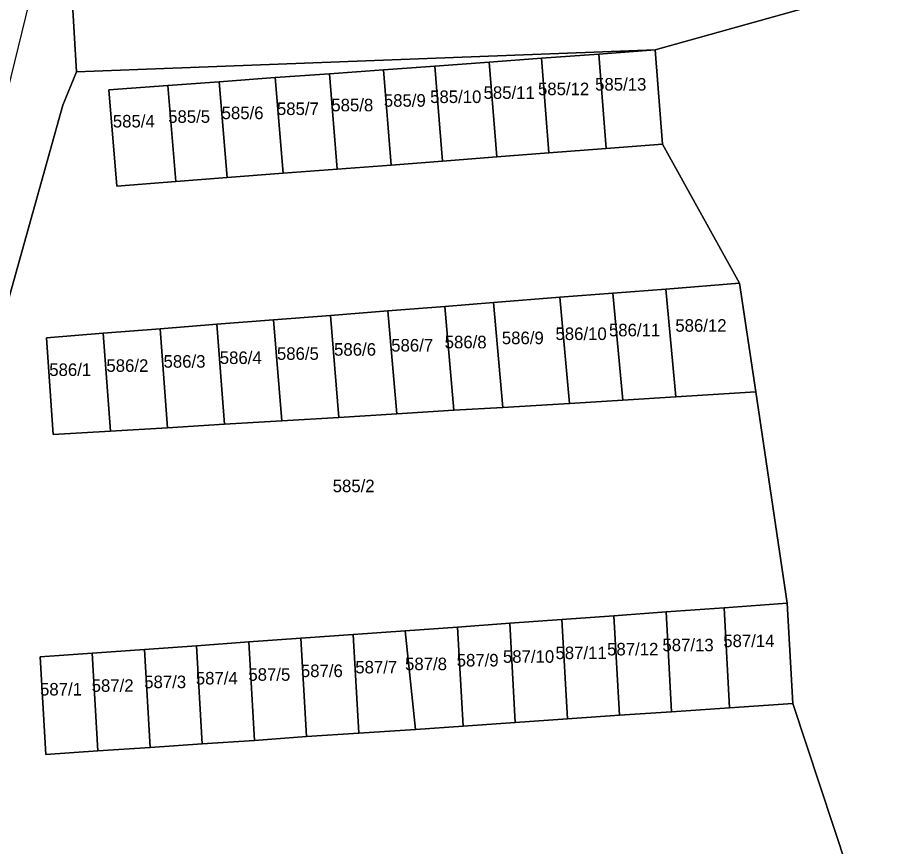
# Model space of a CAD drawing. Extents: x -873642 to -872917, y -1012962 to -1012567.
# Drawn here: x -873069.4 to -873009.9, y -1012699.6 to -1012643.4 of the extents above; entities that cross this region are included whole.
import ezdxf

# ---------------------------------------------------------------- set-up
doc = ezdxf.new("R2010")
doc.units = 0
for name, color, linetype in [('cisla_parcelni_kn', 7, 'Continuous'), ('osy_ulic', 7, 'Continuous'), ('parcely_kn', 7, 'Continuous'), ('stavebni_objekty_ostatni', 7, 'Continuous')]:
    doc.layers.add(name, color=color, linetype=linetype)

msp = doc.modelspace()

# ---------------------------------------------------------------- linework, layer by layer
at = {"layer": 'osy_ulic'}
msp.add_lwpolyline([(-873411.85, -1012822.53), (-873317.85, -1012788.44), (-873277.23, -1012773.91), (-873252.76, -1012767.01), (-873201.18, -1012755.57), (-873115.6, -1012739.3), (-873104.65, -1012731.3), (-873088.93, -1012706.26), (-873080.41, -1012681.66), (-873071.61, -1012653.78), (-873070.57, -1012650.45), (-873066.08, -1012632.13), (-873063.74, -1012625.63), (-873059.56, -1012597.3)], dxfattribs=at)
at = {"layer": 'parcely_kn'}
for points in [[(-873047.57, -1012601.38), (-872987.5, -1012597.44), (-872963.92, -1012595.9), (-872964.43, -1012596.64), (-872989.57, -1012634.71), (-872990.98, -1012635.74), (-873026.14, -1012645.58), (-873065.38, -1012647.07), (-873065.7, -1012641.7), (-873062.75, -1012637.7), (-873058.34, -1012622.19), (-873059.76, -1012619.22), (-873054.28, -1012608.24), (-873052.37, -1012604.41), (-873050.31, -1012602.24)], [(-873047.57, -1012601.38), (-872987.5, -1012597.44), (-872963.92, -1012595.9), (-872964.43, -1012596.64), (-872989.57, -1012634.71), (-872990.98, -1012635.74), (-873026.14, -1012645.58), (-873065.38, -1012647.07), (-873065.7, -1012641.7), (-873062.75, -1012637.7), (-873058.34, -1012622.19), (-873059.76, -1012619.22), (-873054.28, -1012608.24), (-873052.37, -1012604.41), (-873050.31, -1012602.24)], [(-873026.14, -1012645.58), (-873025.64, -1012651.97), (-873029.46, -1012652.26), (-873029.97, -1012645.86)], [(-873026.14, -1012645.58), (-873025.64, -1012651.97), (-873029.46, -1012652.26), (-873029.97, -1012645.86)], [(-873033.86, -1012646.14), (-873033.35, -1012652.56), (-873036.88, -1012652.83), (-873037.4, -1012646.4)], [(-873033.86, -1012646.14), (-873033.35, -1012652.56), (-873036.88, -1012652.83), (-873037.4, -1012646.4)], [(-873029.97, -1012645.86), (-873029.46, -1012652.26), (-873033.35, -1012652.56), (-873033.86, -1012646.14)], [(-873029.97, -1012645.86), (-873029.46, -1012652.26), (-873033.35, -1012652.56), (-873033.86, -1012646.14)], [(-873041.08, -1012646.67), (-873040.56, -1012653.11), (-873044.05, -1012653.38), (-873044.57, -1012646.92)], [(-873041.08, -1012646.67), (-873040.56, -1012653.11), (-873044.05, -1012653.38), (-873044.57, -1012646.92)], [(-873037.4, -1012646.4), (-873036.88, -1012652.83), (-873040.56, -1012653.11), (-873041.08, -1012646.67)], [(-873037.4, -1012646.4), (-873036.88, -1012652.83), (-873040.56, -1012653.11), (-873041.08, -1012646.67)], [(-873051.91, -1012647.45), (-873051.38, -1012653.94), (-873055.17, -1012654.23), (-873055.72, -1012647.73)], [(-873051.91, -1012647.45), (-873051.38, -1012653.94), (-873055.17, -1012654.23), (-873055.72, -1012647.73)], [(-873048.23, -1012647.19), (-873047.7, -1012653.66), (-873051.38, -1012653.94), (-873051.91, -1012647.45)], [(-873048.23, -1012647.19), (-873047.7, -1012653.66), (-873051.38, -1012653.94), (-873051.91, -1012647.45)], [(-873044.57, -1012646.92), (-873044.05, -1012653.38), (-873047.7, -1012653.66), (-873048.23, -1012647.19)], [(-873044.57, -1012646.92), (-873044.05, -1012653.38), (-873047.7, -1012653.66), (-873048.23, -1012647.19)], [(-873059.19, -1012647.98), (-873058.65, -1012654.49), (-873062.64, -1012654.8), (-873063.19, -1012648.27)], [(-873059.19, -1012647.98), (-873058.65, -1012654.49), (-873062.64, -1012654.8), (-873063.19, -1012648.27)], [(-873055.72, -1012647.73), (-873055.17, -1012654.23), (-873058.65, -1012654.49), (-873059.19, -1012647.98)], [(-873055.72, -1012647.73), (-873055.17, -1012654.23), (-873058.65, -1012654.49), (-873059.19, -1012647.98)], [(-873020.42, -1012661.39), (-873019.32, -1012668.75), (-873024.74, -1012669.09), (-873025.43, -1012661.78)], [(-873020.42, -1012661.39), (-873019.32, -1012668.75), (-873024.74, -1012669.09), (-873025.43, -1012661.78)], [(-873029.02, -1012662.06), (-873028.33, -1012669.31), (-873031.96, -1012669.53), (-873032.62, -1012662.34)], [(-873029.02, -1012662.06), (-873028.33, -1012669.31), (-873031.96, -1012669.53), (-873032.62, -1012662.34)], [(-873029.02, -1012662.06), (-873025.43, -1012661.78), (-873024.74, -1012669.09), (-873028.33, -1012669.31)], [(-873029.02, -1012662.06), (-873025.43, -1012661.78), (-873024.74, -1012669.09), (-873028.33, -1012669.31)], [(-873037.12, -1012662.7), (-873036.48, -1012669.8), (-873039.8, -1012670), (-873040.42, -1012662.96)], [(-873037.12, -1012662.7), (-873036.48, -1012669.8), (-873039.8, -1012670), (-873040.42, -1012662.96)], [(-873032.62, -1012662.34), (-873031.96, -1012669.53), (-873036.48, -1012669.8), (-873037.12, -1012662.7)], [(-873032.62, -1012662.34), (-873031.96, -1012669.53), (-873036.48, -1012669.8), (-873037.12, -1012662.7)], [(-873044.27, -1012663.26), (-873043.67, -1012670.24), (-873047.6, -1012670.48), (-873048.17, -1012663.57)], [(-873044.27, -1012663.26), (-873043.67, -1012670.24), (-873047.6, -1012670.48), (-873048.17, -1012663.57)], [(-873040.42, -1012662.96), (-873039.8, -1012670), (-873043.67, -1012670.24), (-873044.27, -1012663.26)], [(-873040.42, -1012662.96), (-873039.8, -1012670), (-873043.67, -1012670.24), (-873044.27, -1012663.26)], [(-873052.02, -1012663.87), (-873051.47, -1012670.71), (-873055.34, -1012670.95), (-873055.87, -1012664.17)], [(-873052.02, -1012663.87), (-873051.47, -1012670.71), (-873055.34, -1012670.95), (-873055.87, -1012664.17)], [(-873048.17, -1012663.57), (-873047.6, -1012670.48), (-873051.47, -1012670.71), (-873052.02, -1012663.87)], [(-873048.17, -1012663.57), (-873047.6, -1012670.48), (-873051.47, -1012670.71), (-873052.02, -1012663.87)], [(-873059.72, -1012664.47), (-873059.22, -1012671.18), (-873063.09, -1012671.42), (-873063.57, -1012664.78)], [(-873059.72, -1012664.47), (-873059.22, -1012671.18), (-873063.09, -1012671.42), (-873063.57, -1012664.78)], [(-873055.87, -1012664.17), (-873055.34, -1012670.95), (-873059.22, -1012671.18), (-873059.72, -1012664.47)], [(-873055.87, -1012664.17), (-873055.34, -1012670.95), (-873059.22, -1012671.18), (-873059.72, -1012664.47)], [(-873063.57, -1012664.78), (-873063.09, -1012671.42), (-873066.96, -1012671.65), (-873067.42, -1012665.08)], [(-873063.57, -1012664.78), (-873063.09, -1012671.42), (-873066.96, -1012671.65), (-873067.42, -1012665.08)], [(-873017.19, -1012683.08), (-873016.82, -1012689.87), (-873021.11, -1012690.16), (-873021.48, -1012683.39)], [(-873017.19, -1012683.08), (-873016.82, -1012689.87), (-873021.11, -1012690.16), (-873021.48, -1012683.39)], [(-873025.4, -1012683.67), (-873025.03, -1012690.43), (-873028.57, -1012690.67), (-873028.94, -1012683.92)], [(-873025.4, -1012683.67), (-873025.03, -1012690.43), (-873028.57, -1012690.67), (-873028.94, -1012683.92)], [(-873021.48, -1012683.39), (-873021.11, -1012690.16), (-873025.03, -1012690.43), (-873025.4, -1012683.67)], [(-873021.48, -1012683.39), (-873021.11, -1012690.16), (-873025.03, -1012690.43), (-873025.4, -1012683.67)], [(-873032.48, -1012684.18), (-873032.1, -1012690.91), (-873035.64, -1012691.16), (-873036.01, -1012684.43)], [(-873032.48, -1012684.18), (-873032.1, -1012690.91), (-873035.64, -1012691.16), (-873036.01, -1012684.43)], [(-873028.94, -1012683.92), (-873028.57, -1012690.67), (-873032.1, -1012690.91), (-873032.48, -1012684.18)], [(-873028.94, -1012683.92), (-873028.57, -1012690.67), (-873032.1, -1012690.91), (-873032.48, -1012684.18)], [(-873039.55, -1012684.69), (-873039.17, -1012691.4), (-873042.41, -1012691.64), (-873043.09, -1012684.94)], [(-873039.55, -1012684.69), (-873039.17, -1012691.4), (-873042.41, -1012691.64), (-873043.09, -1012684.94)], [(-873036.01, -1012684.43), (-873035.64, -1012691.16), (-873039.17, -1012691.4), (-873039.55, -1012684.69)], [(-873036.01, -1012684.43), (-873035.64, -1012691.16), (-873039.17, -1012691.4), (-873039.55, -1012684.69)], [(-873050.17, -1012685.45), (-873049.78, -1012692.12), (-873053.32, -1012692.37), (-873053.71, -1012685.7)], [(-873050.17, -1012685.45), (-873049.78, -1012692.12), (-873053.32, -1012692.37), (-873053.71, -1012685.7)], [(-873046.63, -1012685.19), (-873046.25, -1012691.88), (-873049.78, -1012692.12), (-873050.17, -1012685.45)], [(-873046.63, -1012685.19), (-873046.25, -1012691.88), (-873049.78, -1012692.12), (-873050.17, -1012685.45)], [(-873043.09, -1012684.94), (-873042.41, -1012691.64), (-873046.25, -1012691.88), (-873046.63, -1012685.19)], [(-873043.09, -1012684.94), (-873042.41, -1012691.64), (-873046.25, -1012691.88), (-873046.63, -1012685.19)], [(-873057.25, -1012685.96), (-873056.86, -1012692.61), (-873060.39, -1012692.85), (-873060.78, -1012686.21)], [(-873057.25, -1012685.96), (-873056.86, -1012692.61), (-873060.39, -1012692.85), (-873060.78, -1012686.21)], [(-873053.71, -1012685.7), (-873053.32, -1012692.37), (-873056.86, -1012692.61), (-873057.25, -1012685.96)], [(-873053.71, -1012685.7), (-873053.32, -1012692.37), (-873056.86, -1012692.61), (-873057.25, -1012685.96)], [(-873064.32, -1012686.47), (-873063.93, -1012693.09), (-873067.47, -1012693.33), (-873067.86, -1012686.72)], [(-873064.32, -1012686.47), (-873063.93, -1012693.09), (-873067.47, -1012693.33), (-873067.86, -1012686.72)], [(-873060.78, -1012686.21), (-873060.39, -1012692.85), (-873063.93, -1012693.09), (-873064.32, -1012686.47)], [(-873060.78, -1012686.21), (-873060.39, -1012692.85), (-873063.93, -1012693.09), (-873064.32, -1012686.47)]]:
    msp.add_lwpolyline(points, close=True, dxfattribs=at)
for points in [[(-873079.43, -1012607.12), (-873054.9, -1012604.66), (-873052.37, -1012604.41), (-873054.28, -1012608.24), (-873059.76, -1012619.22), (-873058.34, -1012622.19), (-873062.75, -1012637.7), (-873065.7, -1012641.7), (-873065.38, -1012647.07), (-873066.31, -1012649.31), (-873079.09, -1012694.9), (-873083.74, -1012706.73), (-873087.64, -1012713.81), (-873091.65, -1012719.56), (-873097.47, -1012726.79), (-873099.7, -1012729.49), (-873101.03, -1012731.11), (-873105.65, -1012736.17), (-873110.07, -1012739.5), (-873114.5, -1012741.96), (-873122.26, -1012744.11), (-873135.01, -1012746.72), (-873148.18, -1012749.22), (-873185.58, -1012756.25)], [(-873079.43, -1012607.12), (-873054.9, -1012604.66), (-873052.37, -1012604.41), (-873054.28, -1012608.24), (-873059.76, -1012619.22), (-873058.34, -1012622.19), (-873062.75, -1012637.7), (-873065.7, -1012641.7), (-873065.38, -1012647.07), (-873066.31, -1012649.31), (-873079.09, -1012694.9), (-873083.74, -1012706.73), (-873087.64, -1012713.81), (-873091.65, -1012719.56), (-873097.47, -1012726.79), (-873099.7, -1012729.49), (-873101.03, -1012731.11), (-873105.65, -1012736.17), (-873110.07, -1012739.5), (-873114.5, -1012741.96), (-873122.26, -1012744.11), (-873135.01, -1012746.72), (-873148.18, -1012749.22), (-873185.58, -1012756.25)], [(-873074.59, -1012740.17), (-873069.33, -1012739.79), (-873065.48, -1012733.61), (-873030.18, -1012730.01), (-873032.33, -1012708.94), (-873028.33, -1012708.58), (-873024.28, -1012708.22), (-873020.29, -1012707.86), (-873016.29, -1012707.5), (-873012.61, -1012707.16), (-873013.12, -1012701), (-873016.82, -1012689.87), (-873017.19, -1012683.08), (-873019.32, -1012668.75), (-873020.42, -1012661.39), (-873025.64, -1012651.97), (-873026.14, -1012645.58), (-872990.98, -1012635.74)], [(-873074.59, -1012740.17), (-873069.33, -1012739.79), (-873065.48, -1012733.61), (-873030.18, -1012730.01), (-873032.33, -1012708.94), (-873028.33, -1012708.58), (-873024.28, -1012708.22), (-873020.29, -1012707.86), (-873016.29, -1012707.5), (-873012.61, -1012707.16), (-873013.12, -1012701), (-873016.82, -1012689.87), (-873017.19, -1012683.08), (-873019.32, -1012668.75), (-873020.42, -1012661.39), (-873025.64, -1012651.97), (-873026.14, -1012645.58), (-872990.98, -1012635.74)], [(-873079.09, -1012694.9), (-873066.31, -1012649.31), (-873065.38, -1012647.07), (-873026.14, -1012645.58), (-873029.97, -1012645.86), (-873033.86, -1012646.14), (-873037.4, -1012646.4), (-873041.08, -1012646.67), (-873044.57, -1012646.92), (-873048.23, -1012647.19), (-873051.91, -1012647.45), (-873055.72, -1012647.73), (-873059.19, -1012647.98), (-873063.19, -1012648.27), (-873062.64, -1012654.8), (-873058.65, -1012654.49), (-873055.17, -1012654.23), (-873051.38, -1012653.94), (-873047.7, -1012653.66), (-873044.05, -1012653.38), (-873040.56, -1012653.11), (-873036.88, -1012652.83), (-873033.35, -1012652.56), (-873029.46, -1012652.26), (-873025.64, -1012651.97), (-873020.42, -1012661.39), (-873025.43, -1012661.78), (-873029.02, -1012662.06), (-873032.62, -1012662.34), (-873037.12, -1012662.7), (-873040.42, -1012662.96), (-873044.27, -1012663.26), (-873048.17, -1012663.57), (-873052.02, -1012663.87), (-873055.87, -1012664.17), (-873059.72, -1012664.47), (-873063.57, -1012664.78), (-873067.42, -1012665.08), (-873066.96, -1012671.65), (-873063.09, -1012671.42), (-873059.22, -1012671.18), (-873055.34, -1012670.95), (-873051.47, -1012670.71), (-873047.6, -1012670.48), (-873043.67, -1012670.24), (-873039.8, -1012670), (-873036.48, -1012669.8), (-873031.96, -1012669.53), (-873028.33, -1012669.31), (-873024.74, -1012669.09), (-873019.32, -1012668.75), (-873017.19, -1012683.08), (-873021.48, -1012683.39), (-873025.4, -1012683.67), (-873028.94, -1012683.92), (-873032.48, -1012684.18), (-873036.01, -1012684.43), (-873039.55, -1012684.69), (-873043.09, -1012684.94), (-873046.63, -1012685.19), (-873050.17, -1012685.45), (-873053.71, -1012685.7), (-873057.25, -1012685.96), (-873060.78, -1012686.21), (-873064.32, -1012686.47), (-873067.86, -1012686.72), (-873067.47, -1012693.33), (-873063.93, -1012693.09), (-873060.39, -1012692.85), (-873056.86, -1012692.61), (-873053.32, -1012692.37), (-873049.78, -1012692.12), (-873046.25, -1012691.88), (-873042.41, -1012691.64), (-873039.17, -1012691.4), (-873035.64, -1012691.16), (-873032.1, -1012690.91), (-873028.57, -1012690.67), (-873025.03, -1012690.43), (-873021.11, -1012690.16), (-873016.82, -1012689.87), (-873013.12, -1012701)], [(-873079.09, -1012694.9), (-873066.31, -1012649.31), (-873065.38, -1012647.07), (-873026.14, -1012645.58), (-873029.97, -1012645.86), (-873033.86, -1012646.14), (-873037.4, -1012646.4), (-873041.08, -1012646.67), (-873044.57, -1012646.92), (-873048.23, -1012647.19), (-873051.91, -1012647.45), (-873055.72, -1012647.73), (-873059.19, -1012647.98), (-873063.19, -1012648.27), (-873062.64, -1012654.8), (-873058.65, -1012654.49), (-873055.17, -1012654.23), (-873051.38, -1012653.94), (-873047.7, -1012653.66), (-873044.05, -1012653.38), (-873040.56, -1012653.11), (-873036.88, -1012652.83), (-873033.35, -1012652.56), (-873029.46, -1012652.26), (-873025.64, -1012651.97), (-873020.42, -1012661.39), (-873025.43, -1012661.78), (-873029.02, -1012662.06), (-873032.62, -1012662.34), (-873037.12, -1012662.7), (-873040.42, -1012662.96), (-873044.27, -1012663.26), (-873048.17, -1012663.57), (-873052.02, -1012663.87), (-873055.87, -1012664.17), (-873059.72, -1012664.47), (-873063.57, -1012664.78), (-873067.42, -1012665.08), (-873066.96, -1012671.65), (-873063.09, -1012671.42), (-873059.22, -1012671.18), (-873055.34, -1012670.95), (-873051.47, -1012670.71), (-873047.6, -1012670.48), (-873043.67, -1012670.24), (-873039.8, -1012670), (-873036.48, -1012669.8), (-873031.96, -1012669.53), (-873028.33, -1012669.31), (-873024.74, -1012669.09), (-873019.32, -1012668.75), (-873017.19, -1012683.08), (-873021.48, -1012683.39), (-873025.4, -1012683.67), (-873028.94, -1012683.92), (-873032.48, -1012684.18), (-873036.01, -1012684.43), (-873039.55, -1012684.69), (-873043.09, -1012684.94), (-873046.63, -1012685.19), (-873050.17, -1012685.45), (-873053.71, -1012685.7), (-873057.25, -1012685.96), (-873060.78, -1012686.21), (-873064.32, -1012686.47), (-873067.86, -1012686.72), (-873067.47, -1012693.33), (-873063.93, -1012693.09), (-873060.39, -1012692.85), (-873056.86, -1012692.61), (-873053.32, -1012692.37), (-873049.78, -1012692.12), (-873046.25, -1012691.88), (-873042.41, -1012691.64), (-873039.17, -1012691.4), (-873035.64, -1012691.16), (-873032.1, -1012690.91), (-873028.57, -1012690.67), (-873025.03, -1012690.43), (-873021.11, -1012690.16), (-873016.82, -1012689.87), (-873013.12, -1012701)]]:
    msp.add_lwpolyline(points, dxfattribs=at)
at = {"layer": 'stavebni_objekty_ostatni'}
for points in [[(-873029.46, -1012652.26), (-873029.97, -1012645.86), (-873026.14, -1012645.58), (-873025.64, -1012651.97)], [(-873036.88, -1012652.83), (-873037.4, -1012646.4), (-873033.86, -1012646.14), (-873033.35, -1012652.56)], [(-873033.35, -1012652.56), (-873033.86, -1012646.14), (-873029.97, -1012645.86), (-873029.46, -1012652.26)], [(-873044.05, -1012653.38), (-873044.57, -1012646.92), (-873041.08, -1012646.67), (-873040.56, -1012653.11)], [(-873040.56, -1012653.11), (-873041.08, -1012646.67), (-873037.4, -1012646.4), (-873036.88, -1012652.83)], [(-873051.91, -1012647.45), (-873051.38, -1012653.94), (-873055.17, -1012654.23), (-873055.72, -1012647.73)], [(-873051.38, -1012653.94), (-873051.91, -1012647.45), (-873048.23, -1012647.19), (-873047.7, -1012653.66)], [(-873047.7, -1012653.66), (-873048.23, -1012647.19), (-873044.57, -1012646.92), (-873044.05, -1012653.38)], [(-873059.19, -1012647.98), (-873058.65, -1012654.49), (-873062.64, -1012654.8), (-873063.19, -1012648.27)], [(-873055.72, -1012647.73), (-873055.17, -1012654.23), (-873058.65, -1012654.49), (-873059.19, -1012647.98)], [(-873020.42, -1012661.39), (-873019.32, -1012668.75), (-873024.74, -1012669.09), (-873025.43, -1012661.78)], [(-873031.96, -1012669.53), (-873032.62, -1012662.34), (-873029.02, -1012662.06), (-873028.33, -1012669.31)], [(-873029.02, -1012662.06), (-873025.43, -1012661.78), (-873024.74, -1012669.09), (-873028.33, -1012669.31)], [(-873037.12, -1012662.7), (-873036.48, -1012669.8), (-873039.8, -1012670), (-873040.42, -1012662.96)], [(-873032.62, -1012662.34), (-873031.96, -1012669.53), (-873036.48, -1012669.8), (-873037.12, -1012662.7)], [(-873043.67, -1012670.24), (-873047.6, -1012670.48), (-873048.17, -1012663.57), (-873044.27, -1012663.26)], [(-873040.42, -1012662.96), (-873039.8, -1012670), (-873043.67, -1012670.24), (-873044.27, -1012663.26)], [(-873051.47, -1012670.71), (-873055.34, -1012670.95), (-873055.87, -1012664.17), (-873052.02, -1012663.87)], [(-873048.17, -1012663.57), (-873047.6, -1012670.48), (-873051.47, -1012670.71), (-873052.02, -1012663.87)], [(-873059.72, -1012664.47), (-873059.22, -1012671.18), (-873063.09, -1012671.42), (-873063.57, -1012664.78)], [(-873055.34, -1012670.95), (-873059.22, -1012671.18), (-873059.72, -1012664.47), (-873055.87, -1012664.17)], [(-873063.09, -1012671.42), (-873066.96, -1012671.65), (-873067.42, -1012665.08), (-873063.57, -1012664.78)], [(-873016.82, -1012689.87), (-873021.11, -1012690.16), (-873021.48, -1012683.39), (-873017.19, -1012683.08)], [(-873025.03, -1012690.43), (-873028.57, -1012690.67), (-873028.94, -1012683.92), (-873025.4, -1012683.67)], [(-873021.48, -1012683.39), (-873021.11, -1012690.16), (-873025.03, -1012690.43), (-873025.4, -1012683.67)], [(-873032.1, -1012690.91), (-873035.64, -1012691.16), (-873036.01, -1012684.43), (-873032.48, -1012684.18)], [(-873028.94, -1012683.92), (-873028.57, -1012690.67), (-873032.1, -1012690.91), (-873032.48, -1012684.18)], [(-873039.55, -1012684.69), (-873039.17, -1012691.4), (-873042.41, -1012691.64), (-873043.09, -1012684.94)], [(-873036.01, -1012684.43), (-873035.64, -1012691.16), (-873039.17, -1012691.4), (-873039.55, -1012684.69)], [(-873053.32, -1012692.37), (-873053.71, -1012685.7), (-873050.17, -1012685.45), (-873049.78, -1012692.12)], [(-873050.17, -1012685.45), (-873046.63, -1012685.19), (-873046.25, -1012691.88), (-873049.78, -1012692.12)], [(-873043.09, -1012684.94), (-873042.41, -1012691.64), (-873046.25, -1012691.88), (-873046.63, -1012685.19)], [(-873060.39, -1012692.85), (-873060.78, -1012686.21), (-873057.25, -1012685.96), (-873056.86, -1012692.61)], [(-873057.25, -1012685.96), (-873053.71, -1012685.7), (-873053.32, -1012692.37), (-873056.86, -1012692.61)], [(-873064.32, -1012686.47), (-873063.93, -1012693.09), (-873067.47, -1012693.33), (-873067.86, -1012686.72)], [(-873064.32, -1012686.47), (-873060.78, -1012686.21), (-873060.39, -1012692.85), (-873063.93, -1012693.09)]]:
    msp.add_lwpolyline(points, close=True, dxfattribs=at)

# ---------------------------------------------------------------- texts
at = {"layer": 'cisla_parcelni_kn'}
for s, p in [('585/13', (-873030.221, -1012648.331)), ('585/13', (-873030.221, -1012648.331)), ('585/11', (-873037.783, -1012648.894)), ('585/11', (-873037.783, -1012648.894)), ('585/12', (-873034.096, -1012648.644)), ('585/12', (-873034.096, -1012648.644)), ('585/9', (-873044.546, -1012649.425)), ('585/9', (-873044.546, -1012649.425)), ('585/10', (-873041.408, -1012649.175)), ('585/10', (-873041.408, -1012649.175)), ('585/7', (-873051.796, -1012649.988)), ('585/7', (-873051.796, -1012649.988)), ('585/8', (-873048.108, -1012649.738)), ('585/8', (-873048.108, -1012649.738)), ('585/5', (-873059.171, -1012650.519)), ('585/5', (-873059.171, -1012650.519)), ('585/6', (-873055.546, -1012650.269)), ('585/6', (-873055.546, -1012650.269)), ('585/4', (-873062.921, -1012650.831)), ('585/4', (-873062.921, -1012650.831)), ('586/11', (-873029.283, -1012664.988)), ('586/11', (-873029.283, -1012664.988)), ('586/12', (-873024.783, -1012664.675)), ('586/12', (-873024.783, -1012664.675)), ('586/9', (-873036.546, -1012665.519)), ('586/9', (-873036.546, -1012665.519)), ('586/10', (-873032.908, -1012665.238)), ('586/10', (-873032.908, -1012665.238)), ('586/7', (-873044.046, -1012666.019)), ('586/7', (-873044.046, -1012666.019)), ('586/8', (-873040.421, -1012665.8)), ('586/8', (-873040.421, -1012665.8)), ('586/5', (-873051.796, -1012666.581)), ('586/5', (-873051.796, -1012666.581)), ('586/6', (-873047.921, -1012666.3)), ('586/6', (-873047.921, -1012666.3)), ('586/3', (-873059.483, -1012667.113)), ('586/3', (-873059.483, -1012667.113)), ('586/4', (-873055.671, -1012666.863)), ('586/4', (-873055.671, -1012666.863)), ('586/1', (-873067.233, -1012667.675)), ('586/1', (-873067.233, -1012667.675)), ('586/2', (-873063.358, -1012667.394)), ('586/2', (-873063.358, -1012667.394)), ('585/2', (-873048.015, -1012675.55)), ('585/2', (-873048.015, -1012675.55)), ('587/13', (-873025.658, -1012686.331)), ('587/13', (-873025.658, -1012686.331)), ('587/14', (-873021.533, -1012686.05)), ('587/14', (-873021.533, -1012686.05)), ('587/11', (-873032.908, -1012686.863)), ('587/11', (-873032.908, -1012686.863)), ('587/12', (-873029.408, -1012686.613)), ('587/12', (-873029.408, -1012686.613)), ('587/9', (-873039.608, -1012687.363)), ('587/9', (-873039.608, -1012687.363)), ('587/10', (-873036.471, -1012687.113)), ('587/10', (-873036.471, -1012687.113)), ('587/6', (-873050.171, -1012688.081)), ('587/6', (-873050.171, -1012688.081)), ('587/7', (-873046.483, -1012687.831)), ('587/7', (-873046.483, -1012687.831)), ('587/8', (-873043.108, -1012687.613)), ('587/8', (-873043.108, -1012687.613)), ('587/4', (-873057.296, -1012688.581)), ('587/4', (-873057.296, -1012688.581)), ('587/5', (-873053.733, -1012688.331)), ('587/5', (-873053.733, -1012688.331)), ('587/1', (-873067.858, -1012689.331)), ('587/1', (-873067.858, -1012689.331)), ('587/2', (-873064.358, -1012689.081)), ('587/2', (-873064.358, -1012689.081)), ('587/3', (-873060.796, -1012688.831)), ('587/3', (-873060.796, -1012688.831))]:
    msp.add_text(s, height=0.85, dxfattribs=at).set_placement(p)

doc.saveas('drawing.dxf')
